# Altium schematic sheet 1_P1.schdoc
size 391 x 645 mm; Symbol: Drawing-Symbol_A4; Device: Drawing-Symbol_A4; @Project Name: Ai-Camera; @Page Count: 2; @Update Date: 2026-02-02; @Create Date: 2025-08-22; @Schematic Name: Schematic1; @Page No: 1; @Page Name: P1; Company: EasyEDA.com; Version: V1.0; Page Size: A4; @Create Time: 04:24:12; @Update Time: 05:28:56; Width: 1500; Height: 2500; Region Start: 1; X Region Count: 6; Y Region Count: 4; Blade Width: 10; Title Block Position: 3; @Board Name: Board1
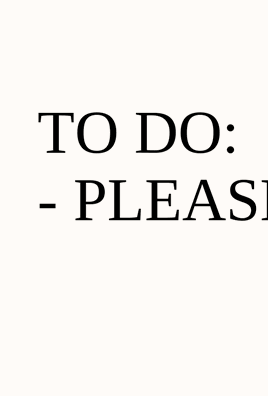
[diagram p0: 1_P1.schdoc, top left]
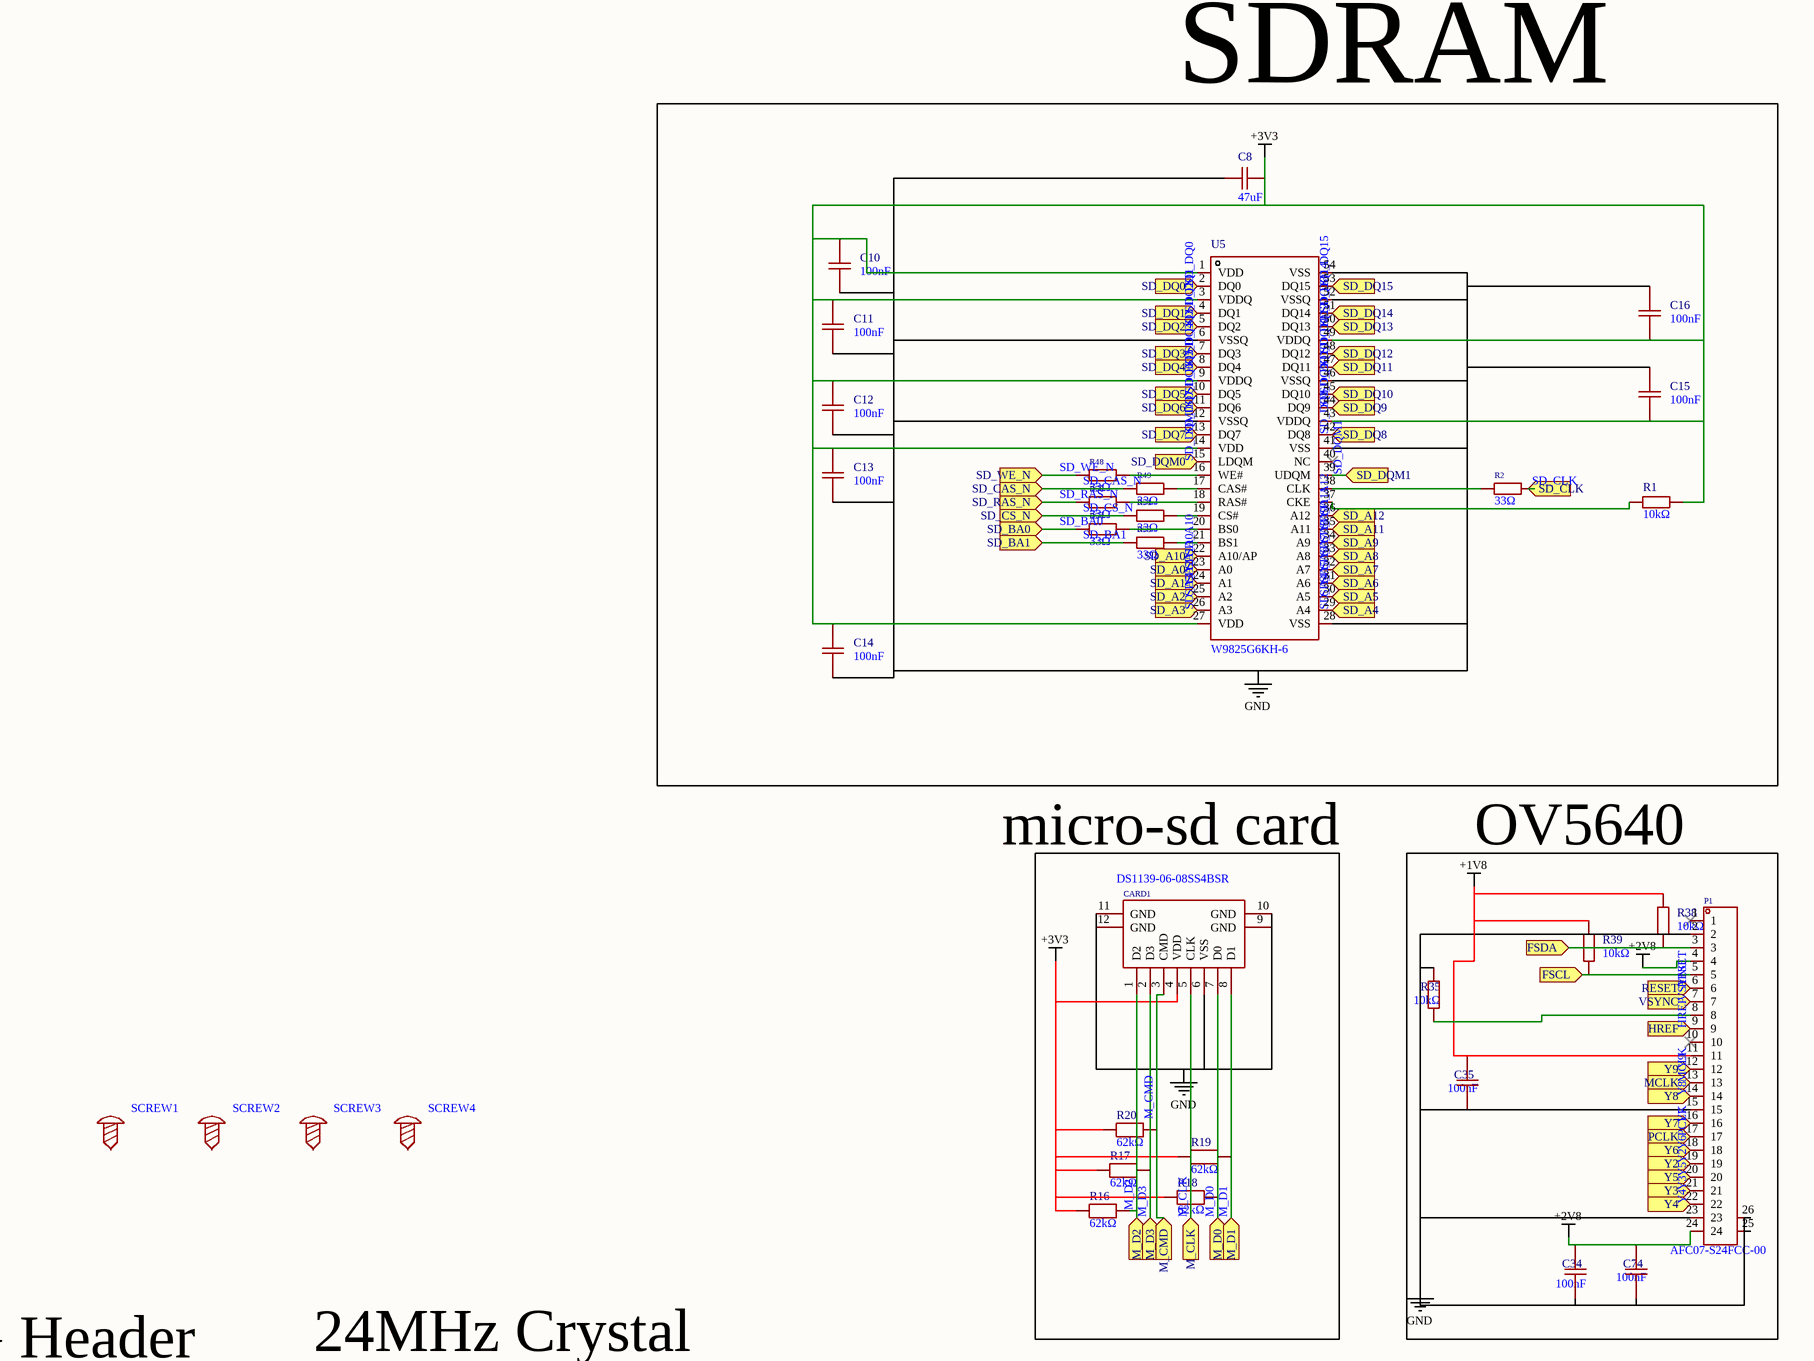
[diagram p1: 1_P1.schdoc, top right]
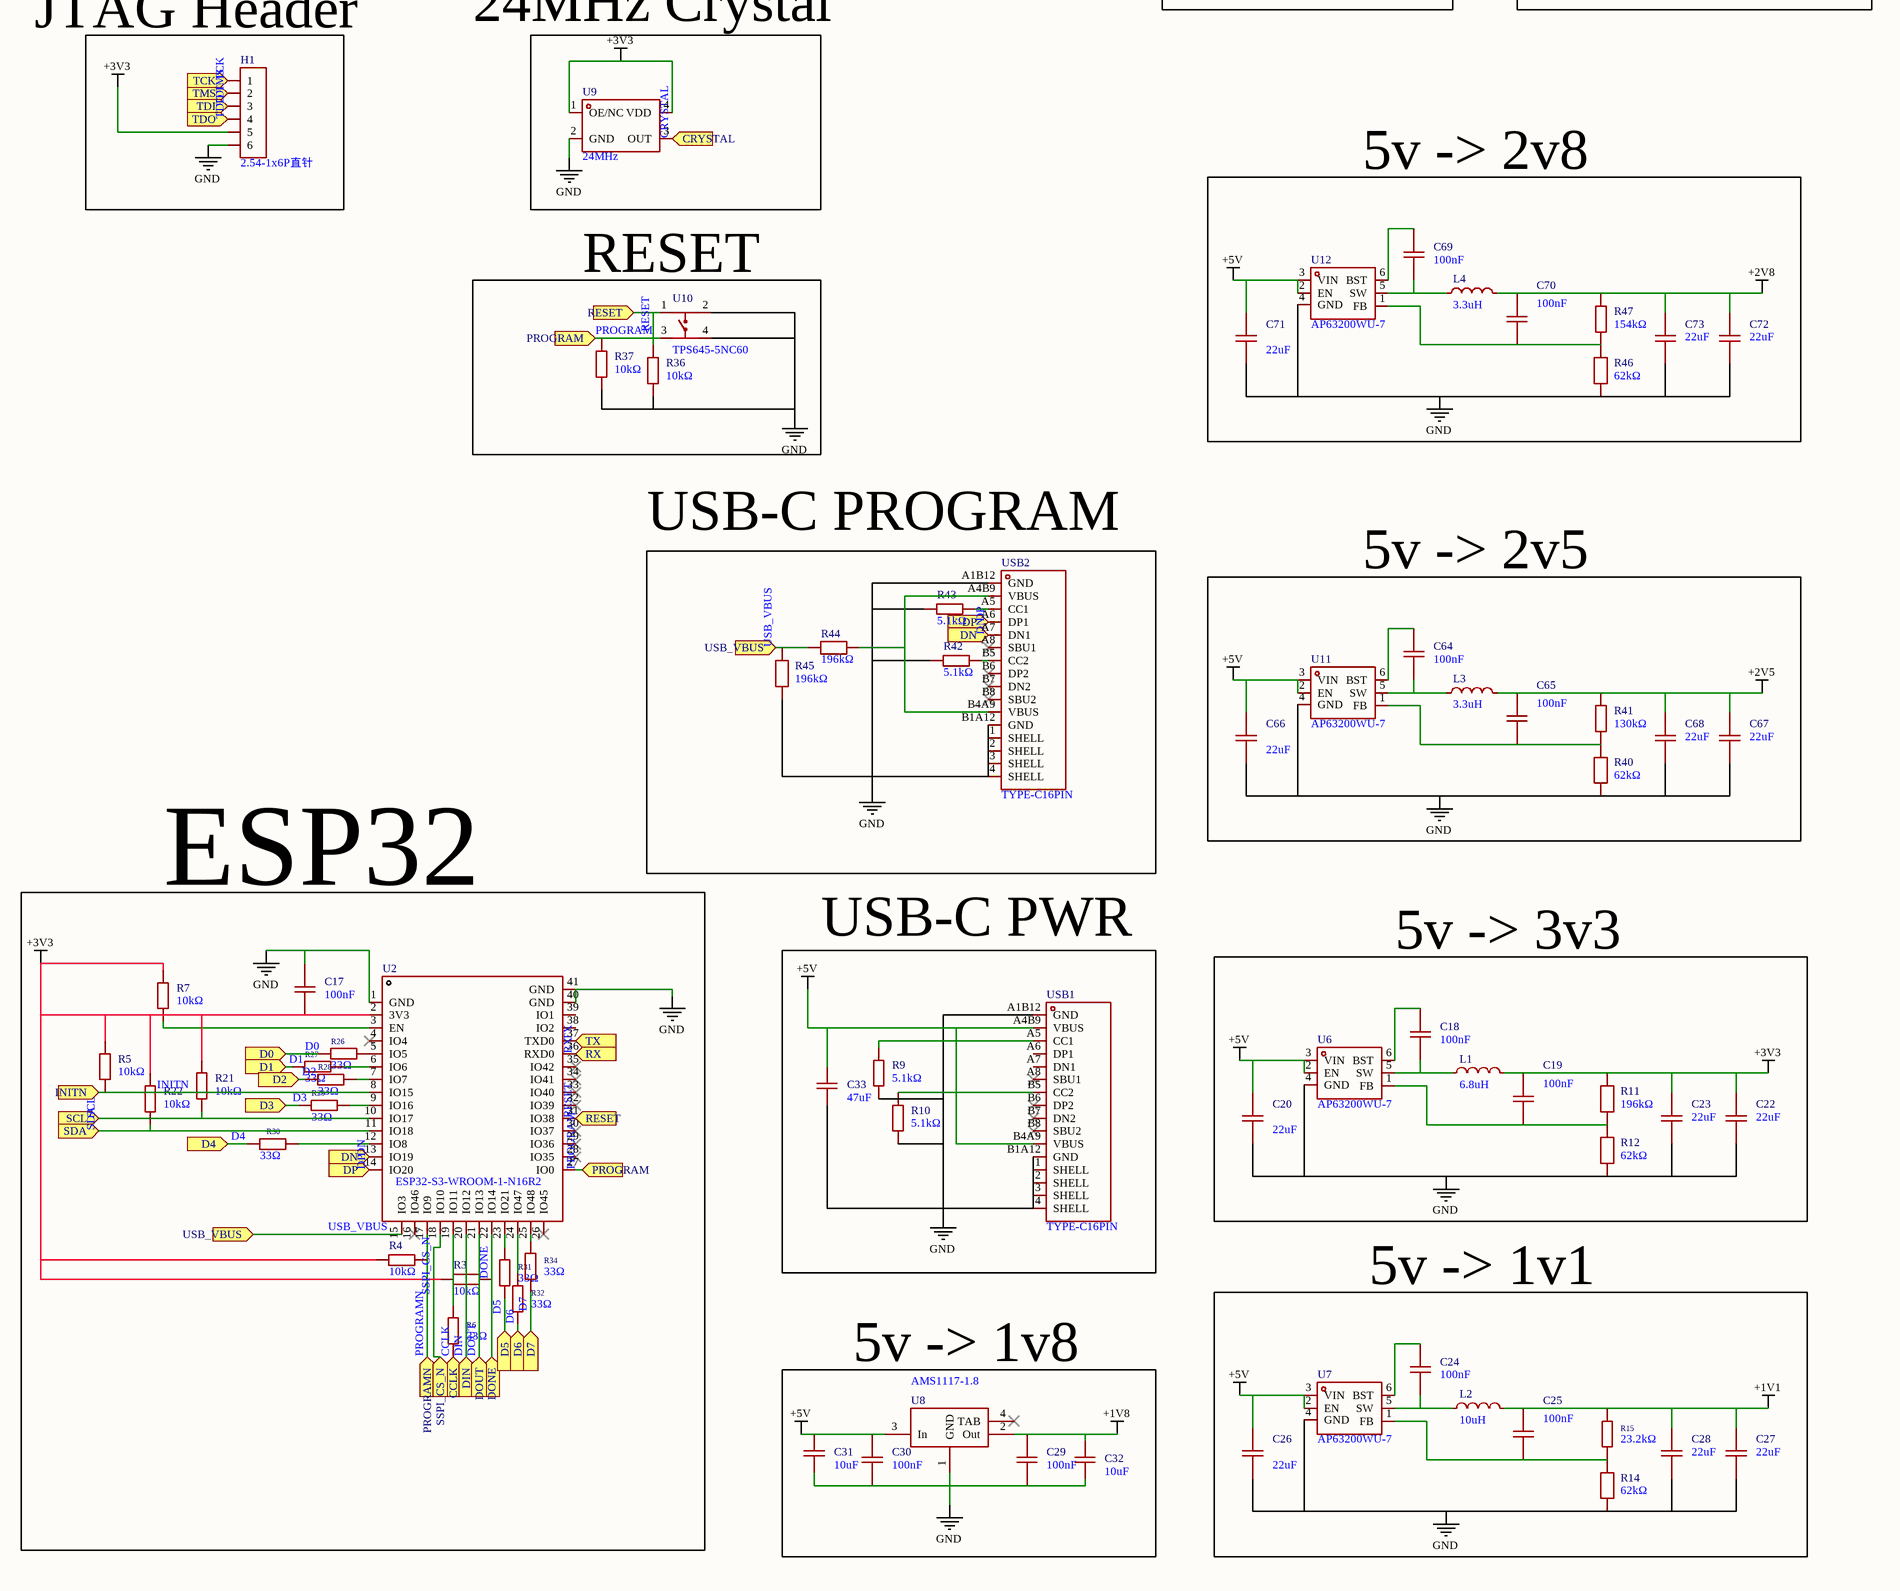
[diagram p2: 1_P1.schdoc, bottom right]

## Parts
C8  47uF  [C0805]
C10  100nF  [C01005]
C11  100nF  [C01005]
C12  100nF  [C01005]
C13  100nF  [C01005]
C14  100nF  [C01005]
C15  100nF  [C01005]
C16  100nF  [C01005]
C17  100nF  [C01005]
C18  100nF  [C01005]
C19  100nF  [C0603]
C20  22uF  [C0603]
C22  22uF  [C0603]
C23  22uF  [C0603]
C24  100nF  [C01005]
C25  100nF  [C0603]
C26  22uF  [C0603]
C27  22uF  [C0603]
C28  22uF  [C0603]
C29  100nF  [C01005]
C30  100nF  [C01005]
C31  10uF  [C0402]
C32  10uF  [C0402]
C33  47uF  [C0805]
C34  100nF  [C01005]
C35  100nF  [C01005]
C64  100nF  [C01005]
C65  100nF  [C0603]
C66  22uF  [C0603]
C67  22uF  [C0603]
C68  22uF  [C0603]
C69  100nF  [C01005]
C70  100nF  [C0603]
C71  22uF  [C0603]
C72  22uF  [C0603]
C73  22uF  [C0603]
C74  100nF  [C01005]
CARD1  DS1139-06-08SS4BSR  [TF-SMD_DS1139-06-08SS4BSR]
H1  2.54-1x6P直针  [HDR-TH_6P-P2.54-V-M-1]
L1  6.8uH  [IND-SMD_L7.0-W6.6]
L2  10uH  [IND-SMD_L7.3-W6.8]
L3  3.3uH  [IND-SMD_L4.5-W4.1_SL0420]
L4  3.3uH  [IND-SMD_L4.5-W4.1_SL0420]
P1  AFC07-S24FCC-00  [FPC-SMD_AFC07-S24FCC-00]
R1  10kΩ  [R0402]
R2  33Ω  [R0402]
R3  10kΩ  [R0402]
R4  10kΩ  [R0402]
R5  10kΩ  [R0402]
R6  33Ω  [R0402]
R7  10kΩ  [R0402]
R9  5.1kΩ  [R0603]
R10  5.1kΩ  [R0603]
R11  196kΩ  [R0603]
R12  62kΩ  [R0603]
R14  62kΩ  [R0603]
R15  23.2kΩ  [R0603]
R16  62kΩ  [R0603]
R17  62kΩ  [R0603]
R18  62kΩ  [R0603]
R19  62kΩ  [R0603]
R20  62kΩ  [R0603]
R21  10kΩ  [R0402]
R22  10kΩ  [R0402]
R26  33Ω  [R0402]
R27  33Ω  [R0402]
R28  33Ω  [R0402]
R29  33Ω  [R0402]
R30  33Ω  [R0402]
R31  33Ω  [R0402]
R32  33Ω  [R0402]
R34  33Ω  [R0402]
R35  10kΩ  [R0402]
R36  10kΩ  [R0402]
R37  10kΩ  [R0402]
R38  10kΩ  [R0402]
R39  10kΩ  [R0402]
R40  62kΩ  [R0603]
R41  130kΩ  [R0402]
R42  5.1kΩ  [R0603]
R43  5.1kΩ  [R0603]
R44  196kΩ  [R0603]
R45  196kΩ  [R0603]
R46  62kΩ  [R0603]
R47  154kΩ  [R0402]
R48  33Ω  [R0402]
R49  33Ω  [R0402]
R50  33Ω  [R0402]
R51  33Ω  [R0402]
R53  33Ω  [R0402]
R54  33Ω  [R0402]
SCREW1  (no value)  [Screw-Hole-M2]
SCREW2  (no value)  [Screw-Hole-M3]
SCREW3  (no value)  [Screw-Hole-M3]
SCREW4  (no value)  [Screw-Hole-M3]
U2  ESP32-S3-WROOM-1-N16R2  [WIRELM-SMD_ESP32-S3-WROOM-1]
U5  W9825G6KH-6  [TSOP-54_L22.2-W10.2-P0.80-LS11.8-BL]
U6  AP63200WU-7  [SOT-23-6_L2.9-W1.6-P0.95-LS2.8-BR]
U7  AP63200WU-7  [SOT-23-6_L2.9-W1.6-P0.95-LS2.8-BR]
U8  AMS1117-1.8  [SOT-223-4_L6.5-W3.5-P2.30-LS7.0-BR]
U9  24MHz  [OSC-SMD_4P-L3.2-W2.5-BL]
U10  TPS645-5NC60  [SW-SMD_4P-L6.0-W6.0-P4.50-LS9.2]
U11  AP63200WU-7  [SOT-23-6_L2.9-W1.6-P0.95-LS2.8-BR]
U12  AP63200WU-7  [SOT-23-6_L2.9-W1.6-P0.95-LS2.8-BR]
USB1  TYPE-C16PIN  [USB-C-SMD_TYPE-C16PIN]
USB2  TYPE-C16PIN  [USB-C-SMD_TYPE-C16PIN]

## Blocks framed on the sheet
SDRAM: C8 C10-C16 R1 R2 R48-R51 R53 R54 U5
OV5640: C34 C35 C74 P1 R35 R38 R39
5v -> 2v8: C69-C73 L4 R46 R47 U12
RESET: R36 R37 U10
USB-C PROGRAM: R42-R45 USB2
5v -> 2v5: C64-C68 L3 R40 R41 U11
ESP32: C17 R3-R7 R21 R22 R26-R32 R34 U2
USB-C PWR: C33 R9 R10 USB1
5v -> 3v3: C18-C20 C22 C23 L1 R11 R12 U6
5v -> 1v1: C24-C28 L2 R14 R15 U7
5v -> 1v8: C29-C32 U8

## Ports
CCLK (in), CRYSTAL (in), D0 (in), D1 (in), D2 (in), D3 (in), D4 (in), D5 (in), D6 (in), D7 (in), DIN (in), DN (in), DONE (in), DOUT (in), DP (in), FSCL (in), FSDA (in), HREF (in), INITN (in), M_CLK (in), M_CMD (in), M_D0 (in), M_D1 (in), M_D2 (in), M_D3 (in), MCLK (in), PCLK (in), PROGRAM (in), PROGRAMN (in), RESET (in), RX (in), SCL (in), SD_A0 (in), SD_A1 (in), SD_A2 (in), SD_A3 (in), SD_A4 (in), SD_A5 (in), SD_A6 (in), SD_A7 (in), SD_A8 (in), SD_A9 (in), SD_A10 (in), SD_A11 (in), SD_A12 (in), SD_BA0 (in), SD_BA1 (in), SD_CAS_N (in), SD_CLK (in), SD_CS_N (in), SD_DQ0 (in), SD_DQ1 (in), SD_DQ2 (in), SD_DQ3 (in), SD_DQ4 (in), SD_DQ5 (in), SD_DQ6 (in), SD_DQ7 (in), SD_DQ8 (in), SD_DQ9 (in), SD_DQ10 (in), SD_DQ11 (in), SD_DQ12 (in), SD_DQ13 (in), SD_DQ14 (in), SD_DQ15 (in), SD_DQM0 (in), SD_DQM1 (in), SD_RAS_N (in), SD_WE_N (in), SDA (in), SSPI_CS_N (in), TCK (in), TDI (in), TDO (in), TMS (in), TX (in), USB_VBUS (in), VSYNC (in), Y2 (in), Y3 (in), Y4 (in), Y5 (in), Y6 (in), Y7 (in), Y8 (in), Y9 (in)

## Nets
+1V1: C25.2 C27.2 C28.2 L2.2 R15.2
+1V8: C29.1 C32.2 C35.1 P1.11 R38.2 R39.2 U8.2(Out)
+2V5: C65.2 C67.2 C68.2 L3.2 R41.2
+2V8: C34.1 C70.2 C72.2 C73.2 C74.1 L4.2 P1.4 P1.24 R47.2
+3V3: C8.1 C10.1 C11.1 C12.1 C13.1 C14.1 C15.2 C16.2 C17.2 C19.2 C22.2 C23.2 CARD1.4(VDD) H1.5 L1.2 R1.2 R3.1 R4.1 R5.2 R7.2 R11.2 R16.2 R17.2 R18.2 R19.2 R20.2 R21.2 R22.2 U2.2(3V3) U5.1(VDD) U5.3(VDDQ) U5.9(VDDQ) U5.14(VDD) U5.27(VDD) U5.43(VDDQ) U5.49(VDDQ) U9.1(OE/NC) U9.4(VDD)
+5V: C20.2 C26.2 C30.1 C31.2 C33.2 C66.2 C71.2 U6.2(EN) U6.3(VIN) U7.2(EN) U7.3(VIN) U8.3(In) U11.2(EN) U11.3(VIN) U12.2(EN) U12.3(VIN) USB1.A4B9(VBUS) USB1.B4A9(VBUS)
GND: C8.2 C10.2 C11.2 C12.2 C13.2 C14.2 C15.1 C16.1 C17.1 C20.1 C22.1 C23.1 C26.1 C27.1 C28.1 C33.1 C34.2 C35.2 C66.1 C67.1 C68.1 C71.1 C72.1 C73.1 C74.2 CARD1.6(VSS) CARD1.9(GND) CARD1.10(GND) CARD1.11(GND) CARD1.12(GND) H1.6 P1.2 P1.15 P1.23 P1.25 P1.26 R9.1 R10.1 R12.1 R14.1 R35.2 R36.2 R37.2 R40.1 R42.2 R43.2 R45.1 R46.1 U2.1(GND) U2.40(GND) U2.41(GND) U5.6(VSSQ) U5.12(VSSQ) U5.28(VSS) U5.41(VSS) U5.46(VSSQ) U5.52(VSSQ) U5.54(VSS) U6.4(GND) U7.4(GND) U8.1(GND) U9.2(GND) U10.2 U10.4 U11.4(GND) U12.4(GND) USB1.1(SHELL) USB1.2(SHELL) USB1.3(SHELL) USB1.4(SHELL) USB1.A1B12(GND) USB1.B1A12(GND) USB2.1(SHELL) USB2.2(SHELL) USB2.3(SHELL) USB2.4(SHELL) USB2.A1B12(GND) USB2.B1A12(GND)
CCLK: R6.1 ; port CCLK
CRYSTAL: U9.3(OUT) ; port CRYSTAL
D0: R26.1 ; port D0
D1: R27.1 ; port D1
D2: R28.1 ; port D2
D3: R29.1 ; port D3
D4: R30.1 ; port D4
D5: R31.1 ; port D5
D6: R32.1 ; port D6
D7: R34.1 ; port D7
DIN: U2.20(IO12) ; port DIN
DN: U2.13(IO19) USB2.A7(DN1) ; port DN
DONE: R3.2 U2.22(IO14) ; port DONE
DOUT: U2.21(IO13) ; port DOUT
DP: U2.14(IO20) USB2.A6(DP1) ; port DP
FSCL: P1.5 R39.1 ; port FSCL
FSDA: P1.3 R38.1 ; port FSDA
HREF: P1.9 ; port HREF
INITN: R5.1 U2.8(IO15) ; port INITN
M_CLK: CARD1.5(CLK) ; port M_CLK
M_CMD: CARD1.3(CMD) R20.1 ; port M_CMD
M_D0: CARD1.7(D0) R18.1 ; port M_D0
M_D1: CARD1.8(D1) R19.1 ; port M_D1
M_D2: CARD1.1(D2) R16.1 ; port M_D2
M_D3: CARD1.2(D3) R17.1 ; port M_D3
MCLK: P1.13 ; port MCLK
PCLK: P1.17 ; port PCLK
PROGRAM: R37.1 U2.27(IO0) U10.3 ; port PROGRAM
PROGRAMN: R4.2 U2.17(IO9) ; port PROGRAMN
RESET: P1.6 R36.1 U2.31(IO38) U10.1 ; port RESET
RX: U2.36(RXD0) ; port RX
SCL: R21.1 U2.10(IO17) ; port SCL
SD_A0: U5.23(A0) ; port SD_A0
SD_A1: U5.24(A1) ; port SD_A1
SD_A2: U5.25(A2) ; port SD_A2
SD_A3: U5.26(A3) ; port SD_A3
SD_A4: U5.29(A4) ; port SD_A4
SD_A5: U5.30(A5) ; port SD_A5
SD_A6: U5.31(A6) ; port SD_A6
SD_A7: U5.32(A7) ; port SD_A7
SD_A8: U5.33(A8) ; port SD_A8
SD_A9: U5.34(A9) ; port SD_A9
SD_A10: U5.22(A10/AP) ; port SD_A10
SD_A11: U5.35(A11) ; port SD_A11
SD_A12: U5.36(A12) ; port SD_A12
SD_BA0: R54.1 ; port SD_BA0
SD_BA1: R53.1 ; port SD_BA1
SD_CAS_N: R49.1 ; port SD_CAS_N
SD_CLK: R2.2 ; port SD_CLK
SD_CS_N: R51.1 ; port SD_CS_N
SD_DQ0: U5.2(DQ0) ; port SD_DQ0
SD_DQ1: U5.4(DQ1) ; port SD_DQ1
SD_DQ2: U5.5(DQ2) ; port SD_DQ2
SD_DQ3: U5.7(DQ3) ; port SD_DQ3
SD_DQ4: U5.8(DQ4) ; port SD_DQ4
SD_DQ5: U5.10(DQ5) ; port SD_DQ5
SD_DQ6: U5.11(DQ6) ; port SD_DQ6
SD_DQ7: U5.13(DQ7) ; port SD_DQ7
SD_DQ8: U5.42(DQ8) ; port SD_DQ8
SD_DQ9: U5.44(DQ9) ; port SD_DQ9
SD_DQ10: U5.45(DQ10) ; port SD_DQ10
SD_DQ11: U5.47(DQ11) ; port SD_DQ11
SD_DQ12: U5.48(DQ12) ; port SD_DQ12
SD_DQ13: U5.50(DQ13) ; port SD_DQ13
SD_DQ14: U5.51(DQ14) ; port SD_DQ14
SD_DQ15: U5.53(DQ15) ; port SD_DQ15
SD_DQM0: U5.15(LDQM) ; port SD_DQM0
SD_DQM1: U5.39(UDQM) ; port SD_DQM1
SD_RAS_N: R50.1 ; port SD_RAS_N
SD_WE_N: R48.1 ; port SD_WE_N
SDA: R22.1 U2.11(IO18) ; port SDA
SSPI_CS_N: U2.18(IO10) ; port SSPI_CS_N
TCK: H1.1 ; port TCK
TDI: H1.3 ; port TDI
TDO: H1.4 ; port TDO
TMS: H1.2 ; port TMS
TX: U2.37(TXD0) ; port TX
USB_VBUS: R44.1 R45.2 U2.15(IO3) ; port USB_VBUS
VSYNC: P1.7 ; port VSYNC
Y2: P1.19 ; port Y2
Y3: P1.21 ; port Y3
Y4: P1.22 ; port Y4
Y5: P1.20 ; port Y5
Y6: P1.18 ; port Y6
Y7: P1.16 ; port Y7
Y8: P1.14 ; port Y8
Y9: P1.12 ; port Y9
NetC18_1: C18.1 U6.6(BST)
NetC18_2: C18.2 L1.1 U6.5(SW)
NetC19_1: C19.1 R11.1 R12.2 U6.1(FB)
NetC24_1: C24.1 U7.6(BST)
NetC24_2: C24.2 L2.1 U7.5(SW)
NetC25_1: C25.1 R14.2 R15.1 U7.1(FB)
NetC29_2: C29.2 C30.2 C31.1 C32.1
NetC64_1: C64.1 U11.6(BST)
NetC64_2: C64.2 L3.1 U11.5(SW)
NetC65_1: C65.1 R40.2 R41.1 U11.1(FB)
NetC69_1: C69.1 U12.6(BST)
NetC69_2: C69.2 L4.1 U12.5(SW)
NetC70_1: C70.1 R46.2 R47.1 U12.1(FB)
NetP1_8: P1.8 R35.1
NetR1_1: R1.1 U5.37(CKE)
NetR2_1: R2.1 U5.38(CLK)
NetR6_2: R6.2 U2.19(IO11)
NetR7_1: R7.1 U2.3(EN)
NetR9_2: R9.2 USB1.A5(CC1)
NetR10_2: R10.2 USB1.B5(CC2)
NetR26_2: R26.2 U2.5(IO5)
NetR27_2: R27.2 U2.6(IO6)
NetR28_2: R28.2 U2.7(IO7)
NetR29_2: R29.2 U2.9(IO16)
NetR30_2: R30.2 U2.12(IO8)
NetR31_2: R31.2 U2.23(IO21)
NetR32_2: R32.2 U2.24(IO47)
NetR34_2: R34.2 U2.25(IO48)
NetR42_1: R42.1 USB2.B5(CC2)
NetR43_1: R43.1 USB2.A5(CC1)
NetR44_2: R44.2 USB2.A4B9(VBUS) USB2.B4A9(VBUS)
NetR48_2: R48.2 U5.16(WE#)
NetR49_2: R49.2 U5.17(CAS#)
NetR50_2: R50.2 U5.18(RAS#)
NetR51_2: R51.2 U5.19(CS#)
NetR53_2: R53.2 U5.21(BS1)
NetR54_2: R54.2 U5.20(BS0)

Not connected (* = marked no-connect by the designer): P1 1* 10*; SCREW1 1; SCREW2 1; SCREW3 1; SCREW4 1; U2 4(IO4)* 16(IO46)* 26(IO45)* 28(IO35)* 29(IO36)* 30(IO37)* 32(IO39)* 33(IO40)* 34(IO41)* 35(IO42)* 38(IO2) 39(IO1); U5 40(NC)*; U8 4(TAB)*; USB1 A6(DP1) A7(DN1) A8(SBU1)* B6(DP2)* B7(DN2)* B8(SBU2)*; USB2 A8(SBU1)* B6(DP2)* B7(DN2)* B8(SBU2)*

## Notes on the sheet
- TO DO:
  - PLEASE CHECK THE POWER ON FPGA
- micro-sd card
- (near H1) JTAG Header
- 24MHz Crystal

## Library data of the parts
C8 C33 = CL21A476MQYNNNE: Manufacturer: SAMSUNG(三星); Add into BOM: yes; Tolerance: ±20%; Voltage Rating: 6.3V; Temperature Coefficient: X5R
C10-C18 C24 C29 C30 C34 C35 C64 C69 C74 = GRM022R60J104KE15D: Manufacturer: muRata(村田); Add into BOM: yes; Tolerance: ±10%; Voltage Rating: 6.3V; Temperature Coefficient: X5R
C19 C25 C65 C70 = TCC0603X7R104K500CT: Manufacturer: CCTC(三环); Add into BOM: yes; Tolerance: ±10%; Voltage Rating: 50V; Temperature Coefficient: X7R
C20 C22 C23 C26-C28 C66-C68 C71-C73 = TCC0603X5R226M6R3CT: Manufacturer: CCTC(三环); Add into BOM: yes; Tolerance: ±20%; Voltage Rating: 6.3V; Temperature Coefficient: X5R
C31 C32 = GRM155R60J106ME44D: Manufacturer: muRata(村田); Add into BOM: yes; Tolerance: ±20%; Voltage Rating: 6.3V; Temperature Coefficient: X5R
CARD1 = DS1139-06-08SS4BSR: Manufacturer: CONNFLY; Add into BOM: yes; Card Connection Mode: Hinged Lid; Card Type: MicroSD Card (TF Card); Connector Type: Connector and Ejector
H1 = 2.54-1x6P直针: Manufacturer: BOOMELE(博穆精密); Symbol: Header-Male-2.54_1x6; Add into BOM: yes; Pin Structure: 1x6P; Pitch: 2.54mm; Circluar Pins/Square Pins: Pin Header; Current Rating: 3A
L1 = FXL0630-6R8-M: Manufacturer: cjiang(长江微电); Add into BOM: yes; Tolerance: ±20%; Current Rating: 5A; Current - Saturation(Isat): 6A; DC Resistance(DCR): 48mΩ; Type: Molded Inductor
L2 = FXL0630-100-M: Manufacturer: cjiang(长江微电); Add into BOM: yes; Tolerance: ±20%; Saturation Current (Isat): 5.5A; Type: Integrated molded inductor
L3 L4 = SL0420-3R3M: Manufacturer: 台湾陆海; Add into BOM: yes; Tolerance: ±20%; Current Rating: 3.5A; Current - Saturation (Isat): 4A
P1 = AFC07-S24FCC-00: Manufacturer: JS(钜硕电子); Symbol: FPC 0.5MM 24P Pull type H2.0mm Under the next; Add into BOM: yes; Locking Feature: Slide Lock; Number of Contacts: 24P; Pitch: 0.5mm; FFC, FCB Thickness: 0.3mm
R1 R3-R5 R7 R21 R22 R35-R39 = 0402WGF1002TCE: Manufacturer: UNI-ROYAL(厚声); Add into BOM: yes; Tolerance: ±1%; Power(Watts): 62.5mW; Voltage-Supply(Max): 50V; Temperature Coefficient: ±100ppm/℃
R2 R6 R26-R32 R34 R48-R51 R53 R54 = 0402WGF330JTCE: Manufacturer: UNI-ROYAL(厚声); Add into BOM: yes; Tolerance: ±1%; Power(Watts): 62.5mW; Voltage-Supply(Max): 50V; Temperature Coefficient: ±100ppm/℃
R9 R10 R42 R43 = 0603WAF5101T5E: Manufacturer: UNI-ROYAL(厚声); Add into BOM: yes; Tolerance: ±1%; Power(Watts): 100mW; Voltage-Supply(Max): 75V; Temperature Coefficient: ±100ppm/℃
R11 R44 R45 = FRC0603F1963TS: Manufacturer: FOJAN(富捷); Add into BOM: yes; Tolerance: ±1%; Power(Watts): 100mW; Voltage-Supply(Max): 75V; Temperature Coefficient: ±100ppm/℃
R12 R14 R16-R20 R40 R46 = FRC0603F6202TS: Manufacturer: FOJAN(富捷); Add into BOM: yes; Tolerance: ±1%; Power(Watts): 100mW; Voltage-Supply(Max): 75V; Temperature Coefficient: ±100ppm/℃
R15 = 0603WAF2322T5E: Manufacturer: UNI-ROYAL(厚声); Add into BOM: yes; Tolerance: ±1%; Power(Watts): 100mW; Voltage-Supply(Max): 75V; Temperature Coefficient: ±100ppm/℃
R41 = RC0402FR-07130KL: Manufacturer: YAGEO(国巨); Add into BOM: yes; Tolerance: ±1%; Power(Watts): 62.5mW; Voltage-Supply(Max): 50V; Temperature Coefficient: ±100ppm/℃
R47 = 0402WGF1543TCE: Manufacturer: UNI-ROYAL(厚声); Add into BOM: yes; Tolerance: ±1%; Power(Watts): 62.5mW; Voltage-Supply(Max): 50V; Temperature Coefficient: ±100ppm/℃
SCREW1 = Screw-Hole-M2: Add into BOM: yes
SCREW2-SCREW4 = Screw-Hole-M3: Convert to PCB: yes
U2 = ESP32-S3-WROOM-1-N16R2: Manufacturer: ESPRESSIF(乐鑫); Symbol: ESP32-S3-WROOM-1(N16R2); Add into BOM: yes
U5 = W9825G6KH-6: Manufacturer: Winbond(华邦); Add into BOM: yes; Memory Size: 256Mbit; Clock Frequency: 166MHz; Voltage - Supply: 3V~3.6V
U6 U7 U11 U12 = AP63200WU-7: Manufacturer: DIODES(美台); Add into BOM: yes; Function: Buck; Voltage - Supply: 3.8V~32V; Output Current: 2A; Frequency - Switching: 500kHz; Number of Outputs: 1; Quiescent Current: 22uA; Switch tube (built-in/external): Built-In; Output Type: Adjustable
U8 = AMS1117-1.8_C6185: Manufacturer: AMS; Add into BOM: yes; Output Type: Fixed; Voltage - Supply: 15V; Output Voltage: 1.8V; Output Current: 1A; Power Supply Rejection Ratio (PSRR): 72dB@(120Hz); Voltage Dropout: 1.3V@(1A); Noise: 0.003%Vout; Output Configuration: Positive; Number of Outputs: 1
U9 = XOS32024000LT00351005: Manufacturer: 同晶; Add into BOM: yes; Normal temperature Frequency Tolerance: ±10ppm; Output Type: CMOS; Voltage - Supply: 1.62V~3.63V; Current - Supply: 5mA; Frequency Stability: ±20ppm
U10 = TPS645-5NC60: Manufacturer: ROCPU Switches(台普); Add into BOM: yes
USB1 USB2 = TYPE-C16PIN: Manufacturer: SHOU HAN(首韩); Add into BOM: yes; Connector Type: Type-C; Protocol Standard: USB 3.1; Gender: Female; Number of Contacts: 16P; Number of Ports: 1; Current Rating-Power: 3A; Voltage Rating: 30V; Connect-Disconnect Life: 10,000 Cycles; Detection color: Black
